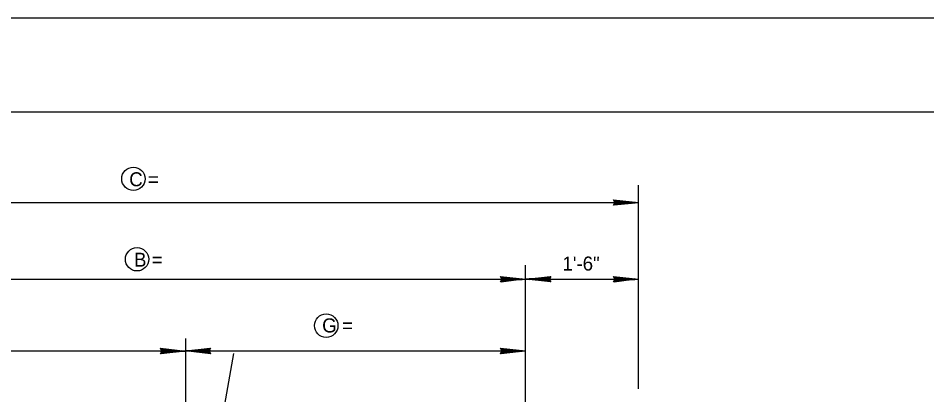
# Model space of a CAD drawing. Extents: x 1.6 to 6.29, y 2.8 to 7.08.
# Drawn here: x 3.058 to 3.864, y 6.747 to 7.081 of the extents above; entities that cross this region are included whole.
import ezdxf

# ---------------------------------------------------------------- set-up
doc = ezdxf.new("R2010")
doc.units = 0
doc.layers.add('Level 1', color=7, linetype='Continuous')
doc.layers.add('Level 5', color=7, linetype='Continuous')

msp = doc.modelspace()

# ---------------------------------------------------------------- linework, layer by layer
at = {"layer": 'Level 1'}
for p, q in [((6.26142, 7.08133), (2.39142, 7.08133)), ((6.18475, 6.998), (2.55808, 6.998)), ((3.608, 6.75217), (3.608, 6.93308)), ((2.80517, 6.91758), (3.60708, 6.91758)), ((3.58592, 6.92008), (3.608, 6.91758)), ((3.58692, 6.91758), (3.58592, 6.92008)), ((3.58592, 6.91758), (3.608, 6.91758)), ((3.608, 6.91758), (3.58592, 6.91517)), ((3.58592, 6.91517), (3.58692, 6.91758)), ((3.58617, 6.91617), (3.6015, 6.91783)), ((3.58625, 6.91975), (3.60275, 6.91783)), ((3.58625, 6.91958), (3.60275, 6.91775)), ((3.58625, 6.91958), (3.60275, 6.91767)), ((3.58625, 6.91933), (3.60275, 6.91742)), ((3.58625, 6.91592), (3.6015, 6.91758)), ((3.58633, 6.91983), (3.60275, 6.91792)), ((3.58742, 6.91775), (3.58642, 6.91942)), ((3.58642, 6.91942), (3.58692, 6.919)), ((3.59158, 6.91842), (3.58683, 6.91867)), ((3.58683, 6.91867), (3.59442, 6.91817)), ((3.58692, 6.919), (3.58742, 6.91817)), ((3.59825, 6.91775), (3.58692, 6.91658)), ((3.58692, 6.91658), (3.58742, 6.91775)), ((3.58708, 6.91833), (3.59158, 6.91842)), ((3.59375, 6.91817), (3.58708, 6.91833)), ((3.58708, 6.91708), (3.59825, 6.91775)), ((3.58742, 6.91908), (3.58717, 6.9175)), ((3.58725, 6.918), (3.59375, 6.91817)), ((3.58725, 6.91783), (3.59717, 6.918)), ((3.59525, 6.91783), (3.58725, 6.918)), ((3.58792, 6.91842), (3.58742, 6.91908)), ((3.58742, 6.91817), (3.58792, 6.91842)), ((3.59442, 6.91817), (3.60417, 6.91775)), ((3.59708, 6.91775), (3.59525, 6.91783)), ((3.59717, 6.918), (3.59708, 6.91775)), ((3.60417, 6.91775), (3.60225, 6.91717)), ((3.58625, 6.91575), (3.60167, 6.91742)), ((3.58633, 6.9155), (3.60167, 6.91717)), ((3.58675, 6.91658), (3.58633, 6.91558)), ((3.58717, 6.9175), (3.58675, 6.91658)), ((3.5925, 6.91708), (3.58708, 6.91708)), ((3.60492, 6.91742), (3.58725, 6.91742)), ((3.58725, 6.91742), (3.5925, 6.91708)), ((3.60225, 6.91717), (3.60492, 6.91742)), ((3.50783, 6.69133), (3.50783, 6.86208)), ((2.80917, 6.8495), (3.60283, 6.8495)), ((3.48567, 6.85183), (3.50783, 6.8495)), ((3.48675, 6.8495), (3.48567, 6.85183)), ((3.48567, 6.8495), (3.50783, 6.8495)), ((3.50783, 6.8495), (3.48567, 6.84708)), ((3.48567, 6.84708), (3.48675, 6.8495)), ((3.486, 6.84825), (3.50142, 6.84975)), ((3.48608, 6.85167), (3.50258, 6.84983)), ((3.48608, 6.85158), (3.50258, 6.84975)), ((3.48608, 6.8515), (3.50258, 6.84975)), ((3.48608, 6.85142), (3.50258, 6.84958)), ((3.48608, 6.85108), (3.50258, 6.84942)), ((3.48608, 6.84792), (3.50142, 6.8495)), ((3.48608, 6.84767), (3.5015, 6.84925)), ((3.48608, 6.84733), (3.5015, 6.84917)), ((3.48658, 6.84858), (3.48608, 6.84742)), ((3.48717, 6.84975), (3.48625, 6.85125)), ((3.48625, 6.85125), (3.48667, 6.85083)), ((3.49133, 6.85042), (3.48658, 6.85067)), ((3.48658, 6.85067), (3.49433, 6.85008)), ((3.48692, 6.8495), (3.48658, 6.84858)), ((3.48667, 6.85083), (3.48717, 6.85008)), ((3.49808, 6.84975), (3.48667, 6.84858)), ((3.48667, 6.84858), (3.48717, 6.84975)), ((3.48683, 6.85025), (3.49133, 6.85042)), ((3.49358, 6.85008), (3.48683, 6.85025)), ((3.48683, 6.849), (3.49808, 6.84975)), ((3.49225, 6.849), (3.48683, 6.849)), ((3.48725, 6.851), (3.48692, 6.8495)), ((3.48708, 6.84992), (3.49358, 6.85008)), ((3.48708, 6.84975), (3.497, 6.84992)), ((3.49508, 6.84975), (3.48708, 6.84992)), ((3.50483, 6.84942), (3.48708, 6.84925)), ((3.48708, 6.84925), (3.49225, 6.849)), ((3.48717, 6.85008), (3.48767, 6.85033)), ((3.48767, 6.85033), (3.48725, 6.851)), ((3.49433, 6.85008), (3.504, 6.84975)), ((3.497, 6.84975), (3.49508, 6.84975)), ((3.497, 6.84992), (3.497, 6.84975)), ((3.504, 6.84975), (3.50208, 6.84917)), ((3.50208, 6.84917), (3.50483, 6.84942)), ((3.508, 6.8495), (3.53008, 6.85208)), ((3.53008, 6.8495), (3.508, 6.8495)), ((3.53008, 6.84708), (3.508, 6.8495)), ((3.51367, 6.84992), (3.51108, 6.84975)), ((3.51108, 6.84975), (3.52858, 6.84975)), ((3.51167, 6.84942), (3.51367, 6.84992)), ((3.5215, 6.849), (3.51167, 6.84942)), ((3.5295, 6.84733), (3.51317, 6.84925)), ((3.5295, 6.84742), (3.51317, 6.84925)), ((3.5295, 6.8475), (3.51317, 6.84925)), ((3.52958, 6.84792), (3.51325, 6.84958)), ((3.5295, 6.84767), (3.51325, 6.8495)), ((3.5295, 6.85158), (3.51425, 6.84992)), ((3.5295, 6.85142), (3.51425, 6.84975)), ((3.52958, 6.85108), (3.51433, 6.8495)), ((3.52958, 6.85083), (3.51433, 6.84925)), ((3.51758, 6.84925), (3.52883, 6.8505)), ((3.52883, 6.85008), (3.51758, 6.84925)), ((3.51875, 6.84917), (3.51875, 6.84942)), ((3.51875, 6.84942), (3.52058, 6.84925)), ((3.52858, 6.84925), (3.51875, 6.84917)), ((3.52058, 6.84925), (3.52858, 6.84917)), ((3.52892, 6.8485), (3.5215, 6.849)), ((3.52858, 6.84917), (3.52217, 6.849)), ((3.52217, 6.849), (3.52883, 6.84883)), ((3.52858, 6.84975), (3.52342, 6.85008)), ((3.52342, 6.85008), (3.52883, 6.85008)), ((3.52883, 6.84883), (3.52417, 6.84867)), ((3.52417, 6.84867), (3.52892, 6.8485)), ((3.5285, 6.849), (3.52783, 6.84875)), ((3.52783, 6.84875), (3.52833, 6.84817)), ((3.52833, 6.84817), (3.52858, 6.84958)), ((3.52883, 6.8505), (3.5285, 6.84925)), ((3.5285, 6.84925), (3.52933, 6.84783)), ((3.52883, 6.84825), (3.5285, 6.849)), ((3.52858, 6.84958), (3.52908, 6.8505)), ((3.53008, 6.85208), (3.52883, 6.8495)), ((3.52883, 6.8495), (3.53008, 6.84708)), ((3.52933, 6.84783), (3.52883, 6.84825)), ((3.52908, 6.8505), (3.5295, 6.85158)), ((3.58583, 6.85183), (3.60792, 6.8495)), ((3.58692, 6.8495), (3.58583, 6.85183)), ((3.58583, 6.8495), (3.60792, 6.8495)), ((3.60792, 6.8495), (3.58583, 6.84708)), ((3.58583, 6.84708), (3.58692, 6.8495)), ((3.58617, 6.85158), (3.60267, 6.84975)), ((3.58617, 6.8515), (3.60267, 6.84975)), ((3.58617, 6.85142), (3.60267, 6.84958)), ((3.58617, 6.85108), (3.60267, 6.84942)), ((3.58617, 6.84825), (3.6015, 6.84975)), ((3.58617, 6.84792), (3.6015, 6.8495)), ((3.58617, 6.84767), (3.6015, 6.84925)), ((3.58625, 6.85167), (3.60267, 6.84983)), ((3.58625, 6.84733), (3.6015, 6.84917)), ((3.58667, 6.84858), (3.58625, 6.84742)), ((3.58725, 6.84975), (3.58633, 6.85125)), ((3.58633, 6.85125), (3.58683, 6.85083)), ((3.58708, 6.8495), (3.58667, 6.84858)), ((3.5915, 6.85042), (3.58675, 6.85067)), ((3.58675, 6.85067), (3.59433, 6.85008)), ((3.58683, 6.85083), (3.58725, 6.85008)), ((3.59817, 6.84975), (3.58683, 6.84858)), ((3.58683, 6.84858), (3.58725, 6.84975)), ((3.58692, 6.85025), (3.5915, 6.85042)), ((3.5935, 6.85008), (3.58692, 6.85025)), ((3.58692, 6.849), (3.59817, 6.84975)), ((3.59242, 6.849), (3.58692, 6.849)), ((3.58742, 6.851), (3.58708, 6.8495)), ((3.58717, 6.84992), (3.5935, 6.85008)), ((3.58717, 6.84975), (3.59708, 6.84992)), ((3.59517, 6.84975), (3.58717, 6.84992)), ((3.60483, 6.84942), (3.58717, 6.84925)), ((3.58717, 6.84925), (3.59242, 6.849)), ((3.58725, 6.85008), (3.58783, 6.85033)), ((3.58783, 6.85033), (3.58742, 6.851)), ((3.59433, 6.85008), (3.60417, 6.84975)), ((3.597, 6.84975), (3.59517, 6.84975)), ((3.59708, 6.84992), (3.597, 6.84975)), ((3.60417, 6.84975), (3.60217, 6.84917)), ((3.60217, 6.84917), (3.60483, 6.84942)), ((3.20608, 6.79692), (3.20608, 6.59533)), ((2.90642, 6.78583), (3.50775, 6.78583)), ((3.18383, 6.78817), (3.20608, 6.78575)), ((3.185, 6.78575), (3.18383, 6.78817)), ((3.18383, 6.78575), (3.20608, 6.78575)), ((3.18383, 6.78325), (3.185, 6.78575)), ((3.20617, 6.78575), (3.18392, 6.78325)), ((3.18417, 6.78433), (3.19967, 6.786)), ((3.18425, 6.78783), (3.20083, 6.786)), ((3.18425, 6.78775), (3.20083, 6.78592)), ((3.18425, 6.78767), (3.20083, 6.78583)), ((3.18425, 6.78742), (3.20083, 6.78558)), ((3.18425, 6.78408), (3.19967, 6.78575)), ((3.18425, 6.78383), (3.19975, 6.7855)), ((3.18433, 6.78792), (3.20083, 6.78608)), ((3.18433, 6.78358), (3.19975, 6.78533)), ((3.18475, 6.78475), (3.18433, 6.78367)), ((3.18542, 6.78592), (3.18442, 6.7875)), ((3.18442, 6.7875), (3.18492, 6.78717)), ((3.18517, 6.78567), (3.18475, 6.78475)), ((3.18967, 6.78667), (3.18483, 6.78692)), ((3.18483, 6.78692), (3.1925, 6.78633)), ((3.18492, 6.78717), (3.18542, 6.78633)), ((3.19633, 6.78592), (3.18492, 6.78475)), ((3.18492, 6.78475), (3.18542, 6.78592)), ((3.18508, 6.7865), (3.18967, 6.78667)), ((3.19175, 6.78633), (3.18508, 6.7865)), ((3.18508, 6.78517), (3.19633, 6.78592)), ((3.1905, 6.78517), (3.18508, 6.78517)), ((3.1855, 6.78725), (3.18517, 6.78567)), ((3.18533, 6.78617), (3.19175, 6.78633)), ((3.18533, 6.786), (3.19525, 6.78617)), ((3.19333, 6.786), (3.18533, 6.78617)), ((3.20308, 6.78558), (3.18533, 6.7855)), ((3.18533, 6.7855), (3.1905, 6.78517)), ((3.18542, 6.78633), (3.18592, 6.78658)), ((3.18592, 6.78658), (3.1855, 6.78725)), ((3.1925, 6.78633), (3.20233, 6.78592)), ((3.19517, 6.78592), (3.19333, 6.786)), ((3.19525, 6.78617), (3.19517, 6.78592)), ((3.20233, 6.78592), (3.20033, 6.78533)), ((3.20033, 6.78533), (3.20308, 6.78558)), ((3.20608, 6.78592), (3.22817, 6.78842)), ((3.22817, 6.78583), (3.20608, 6.78583)), ((3.22817, 6.78342), (3.20608, 6.78583)), ((3.20625, 6.54067), (3.24892, 6.7835)), ((3.21175, 6.78625), (3.20908, 6.786)), ((3.20908, 6.786), (3.22667, 6.78608)), ((3.20975, 6.78567), (3.21175, 6.78625)), ((3.21958, 6.78525), (3.20975, 6.78567)), ((3.22767, 6.78375), (3.21125, 6.78558)), ((3.22767, 6.78383), (3.21125, 6.78558)), ((3.22767, 6.78367), (3.21125, 6.7855)), ((3.22775, 6.78417), (3.21133, 6.78592)), ((3.22767, 6.78392), (3.21133, 6.78575)), ((3.22767, 6.78792), (3.21233, 6.78625)), ((3.22767, 6.78775), (3.21233, 6.78608)), ((3.22775, 6.7875), (3.21242, 6.78583)), ((3.22775, 6.78725), (3.21242, 6.78558)), ((3.21567, 6.78558), (3.227, 6.78683)), ((3.22692, 6.78642), (3.21567, 6.78558)), ((3.21683, 6.78542), (3.21683, 6.78567)), ((3.21683, 6.78567), (3.21875, 6.78558)), ((3.22667, 6.78558), (3.21683, 6.78542)), ((3.21875, 6.78558), (3.22667, 6.78542)), ((3.22708, 6.78467), (3.21958, 6.78525)), ((3.22667, 6.78542), (3.22033, 6.78525)), ((3.22033, 6.78525), (3.22692, 6.78508)), ((3.22667, 6.78608), (3.2215, 6.78642)), ((3.2215, 6.78642), (3.22692, 6.78642)), ((3.22692, 6.78508), (3.22225, 6.78492)), ((3.22225, 6.78492), (3.22708, 6.78467)), ((3.22658, 6.78525), (3.226, 6.785)), ((3.226, 6.785), (3.22642, 6.78433)), ((3.22642, 6.78433), (3.22675, 6.78592)), ((3.227, 6.78683), (3.22658, 6.78558)), ((3.22658, 6.78558), (3.2275, 6.78408)), ((3.227, 6.78442), (3.22658, 6.78525)), ((3.22675, 6.78592), (3.22717, 6.78683)), ((3.22817, 6.78833), (3.227, 6.78583)), ((3.227, 6.78583), (3.22817, 6.78342)), ((3.2275, 6.78408), (3.227, 6.78442)), ((3.22717, 6.78683), (3.22767, 6.78792)), ((3.4855, 6.78825), (3.50775, 6.78583)), ((3.48667, 6.78583), (3.4855, 6.78825)), ((3.4855, 6.78583), (3.50775, 6.78583)), ((3.50775, 6.78583), (3.4855, 6.78333)), ((3.4855, 6.78333), (3.48667, 6.78583)), ((3.48583, 6.78442), (3.50133, 6.78608)), ((3.48592, 6.78792), (3.5025, 6.78608)), ((3.48592, 6.78783), (3.5025, 6.786)), ((3.48592, 6.78775), (3.5025, 6.78592)), ((3.48592, 6.7875), (3.5025, 6.78567)), ((3.48592, 6.78417), (3.50133, 6.78583)), ((3.48592, 6.78392), (3.50142, 6.78558)), ((3.486, 6.788), (3.5025, 6.78617)), ((3.486, 6.78367), (3.50142, 6.78542)), ((3.48642, 6.78483), (3.486, 6.78375)), ((3.48708, 6.786), (3.48608, 6.78758)), ((3.48608, 6.78758), (3.48658, 6.78725)), ((3.48683, 6.78575), (3.48642, 6.78483)), ((3.49133, 6.78675), (3.4865, 6.787)), ((3.4865, 6.787), (3.49417, 6.78642)), ((3.48658, 6.78725), (3.48708, 6.78642)), ((3.498, 6.786), (3.48658, 6.78483)), ((3.48658, 6.78483), (3.48708, 6.786)), ((3.48675, 6.78658), (3.49133, 6.78675)), ((3.49342, 6.78642), (3.48675, 6.78658)), ((3.48675, 6.78525), (3.498, 6.786)), ((3.49217, 6.78525), (3.48675, 6.78525)), ((3.48717, 6.78733), (3.48683, 6.78575)), ((3.487, 6.78625), (3.49342, 6.78642)), ((3.487, 6.78608), (3.49692, 6.78625)), ((3.495, 6.78608), (3.487, 6.78625)), ((3.50475, 6.78567), (3.487, 6.78558)), ((3.487, 6.78558), (3.49217, 6.78525)), ((3.48708, 6.78642), (3.48758, 6.78667)), ((3.48758, 6.78667), (3.48717, 6.78733)), ((3.49417, 6.78642), (3.504, 6.786)), ((3.49683, 6.786), (3.495, 6.78608)), ((3.49692, 6.78625), (3.49683, 6.786)), ((3.504, 6.786), (3.502, 6.78542)), ((3.502, 6.78542), (3.50475, 6.78567))]:
    msp.add_line(p, q, dxfattribs=at)
for centre, radius in [((3.15978, 6.9387), 0.01036), ((3.16301, 6.86723), 0.01036), ((3.33087, 6.80831), 0.01042)]:
    msp.add_circle(centre, radius, dxfattribs=at)

# ---------------------------------------------------------------- texts
msp.add_text('1\'-6"', height=0.012416, dxfattribs=at).set_placement((3.5405, 6.85725))
at = {"layer": 'Level 5'}
for s, height, p in [('C =      ', 0.012416, (3.15608, 6.93208)), ('B =      ', 0.012416, (3.16033, 6.86067)), ('G =      ', 0.0125, (3.32725, 6.80225))]:
    msp.add_text(s, height=height, dxfattribs=at).set_placement(p)

doc.saveas('drawing.dxf')
